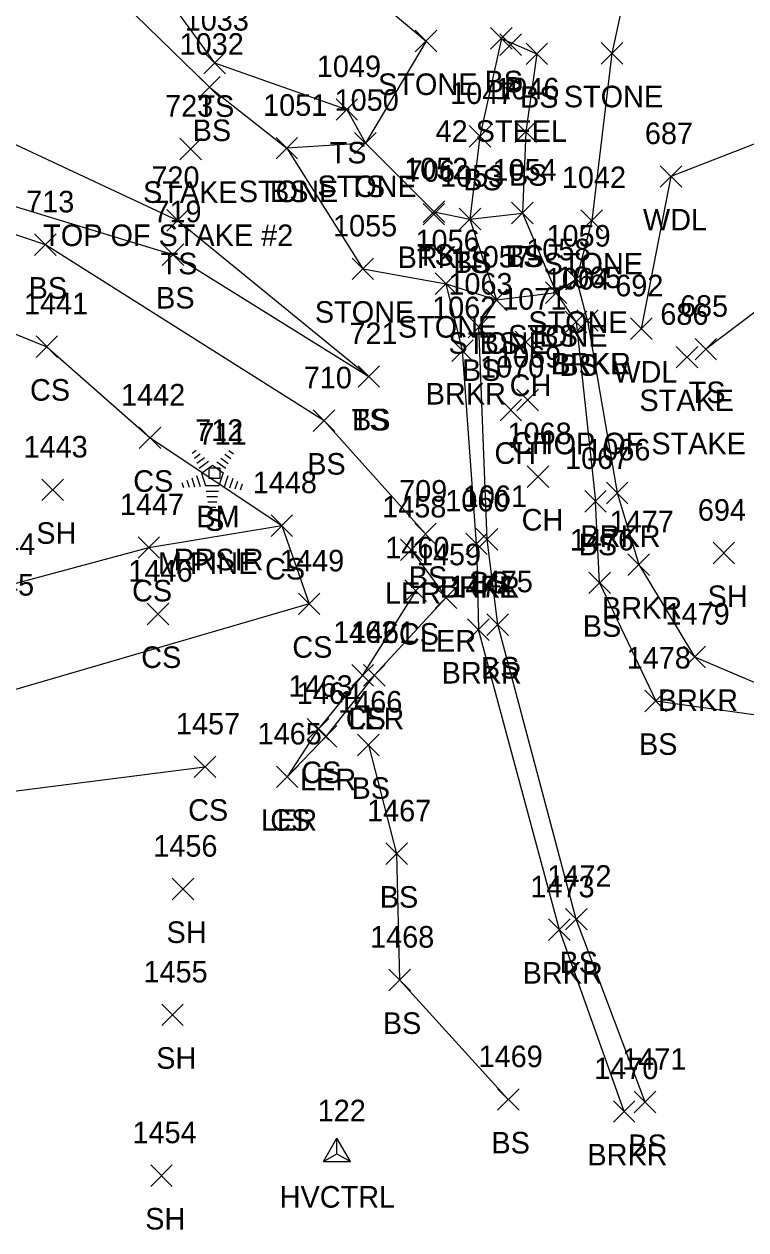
# Model space of a CAD drawing. Extents: x 1485624 to 1495982, y 886445 to 890805.
# Drawn here: x 1495677.5 to 1495744.5, y 890408.1 to 890519.9 of the extents above; entities that cross this region are included whole.
import ezdxf

# ---------------------------------------------------------------- set-up
doc = ezdxf.new("R2010")
doc.units = 0
for name, color, linetype in [('C_A', 7, 'Continuous'), ('C_C', 7, 'Continuous'), ('C_I', 7, 'Continuous'), ('CPBM', 7, 'Continuous'), ('CPSM', 7, 'Continuous'), ('D_A', 7, 'Continuous'), ('D_C', 7, 'Continuous'), ('D_TIC', 7, 'Continuous'), ('E_TIC', 7, 'Continuous'), ('L_A', 7, 'Continuous'), ('L_C', 7, 'Continuous'), ('L_I', 7, 'Continuous'), ('L_TIC', 7, 'Continuous'), ('LARO', 7, 'Continuous'), ('LASF', 7, 'Continuous'), ('LAWA', 7, 'Continuous'), ('LAWE', 7, 'Continuous'), ('LELB', 7, 'Continuous'), ('LTC', 7, 'Continuous'), ('P_I', 7, 'Continuous')]:
    doc.layers.add(name, color=color, linetype=linetype)

msp = doc.modelspace()

# ---------------------------------------------------------------- linework, layer by layer
at = {"layer": 'CPBM'}
for p, q in [((1495694.68, 890477.73), (1495694.68, 890478.73)), ((1495694.68, 890478.73), (1495695.68, 890478.73)), ((1495695.68, 890477.73), (1495694.68, 890477.73)), ((1495695.18, 890478.23), (1495695.18, 890478.23)), ((1495695.18, 890478.23), (1495695.18, 890478.23)), ((1495695.68, 890478.73), (1495695.68, 890477.73))]:
    msp.add_line(p, q, dxfattribs=at)
at = {"layer": 'CPSM'}
for p, q in [((1495705.29, 890414.44), (1495706.54, 890416.6)), ((1495707.79, 890414.44), (1495706.54, 890416.6)), ((1495706.54, 890415.16), (1495706.54, 890416.6)), ((1495705.29, 890414.44), (1495706.54, 890415.16)), ((1495706.54, 890415.16), (1495706.54, 890415.16)), ((1495706.54, 890415.16), (1495707.79, 890414.44)), ((1495705.29, 890414.44), (1495707.79, 890414.44))]:
    msp.add_line(p, q, dxfattribs=at)
at = {"layer": 'D_TIC'}
for points in [[(1495721.65, 890516.95), (1495723.65, 890518.95)], [(1495723.65, 890516.95), (1495721.65, 890518.95)]]:
    msp.add_lwpolyline(points, dxfattribs=at)
at = {"layer": 'E_TIC'}
for points in [[(1495691.97, 890507.29), (1495693.97, 890509.29)], [(1495693.97, 890507.29), (1495691.97, 890509.29)], [(1495737.99, 890487.99), (1495739.99, 890489.99)], [(1495739.99, 890487.99), (1495737.99, 890489.99)]]:
    msp.add_lwpolyline(points, dxfattribs=at)
at = {"layer": 'L_TIC'}
for points in [[(1495713.8, 890517.29), (1495715.8, 890519.29)], [(1495715.8, 890517.29), (1495713.8, 890519.29)], [(1495720.78, 890517.54), (1495722.78, 890519.54)], [(1495722.78, 890517.54), (1495720.78, 890519.54)], [(1495720.78, 890517.54), (1495722.78, 890519.54)], [(1495722.78, 890517.54), (1495720.78, 890519.54)], [(1495724.07, 890516.11), (1495726.07, 890518.11)], [(1495726.07, 890516.11), (1495724.07, 890518.11)], [(1495731.03, 890516.15), (1495733.03, 890518.15)], [(1495733.03, 890516.15), (1495731.03, 890518.15)], [(1495694.19, 890515.26), (1495696.19, 890517.26)], [(1495696.19, 890515.26), (1495694.19, 890517.26)], [(1495693.72, 890513.02), (1495695.72, 890515.02)], [(1495695.72, 890513.02), (1495693.72, 890515.02)], [(1495706.45, 890510.95), (1495708.45, 890512.95)], [(1495708.45, 890510.95), (1495706.45, 890512.95)], [(1495718.8, 890508.46), (1495720.8, 890510.46)], [(1495720.8, 890508.46), (1495718.8, 890510.46)], [(1495723.04, 890508.88), (1495725.04, 890510.88)], [(1495725.04, 890508.88), (1495723.04, 890510.88)], [(1495700.89, 890507.36), (1495702.89, 890509.36)], [(1495702.89, 890507.36), (1495700.89, 890509.36)], [(1495700.89, 890507.36), (1495702.89, 890509.36)], [(1495702.89, 890507.36), (1495700.89, 890509.36)], [(1495708.18, 890507.83), (1495710.18, 890509.83)], [(1495710.18, 890507.83), (1495708.18, 890509.83)], [(1495708.18, 890507.83), (1495710.18, 890509.83)], [(1495710.18, 890507.83), (1495708.18, 890509.83)], [(1495736.5, 890504.74), (1495738.5, 890506.74)], [(1495738.5, 890504.74), (1495736.5, 890506.74)], [(1495714.54, 890501.47), (1495716.54, 890503.47)], [(1495716.54, 890501.47), (1495714.54, 890503.47)], [(1495690.78, 890500.67), (1495692.78, 890502.67)], [(1495692.78, 890500.67), (1495690.78, 890502.67)], [(1495714.52, 890501.25), (1495716.52, 890503.25)], [(1495716.52, 890501.25), (1495714.52, 890503.25)], [(1495717.87, 890500.79), (1495719.87, 890502.79)], [(1495719.87, 890500.79), (1495717.87, 890502.79)], [(1495717.87, 890500.79), (1495719.87, 890502.79)], [(1495719.87, 890500.79), (1495717.87, 890502.79)], [(1495722.73, 890501.35), (1495724.73, 890503.35)], [(1495724.73, 890501.35), (1495722.73, 890503.35)], [(1495722.73, 890501.35), (1495724.73, 890503.35)], [(1495724.73, 890501.35), (1495722.73, 890503.35)], [(1495729.16, 890500.66), (1495731.16, 890502.66)], [(1495731.16, 890500.66), (1495729.16, 890502.66)], [(1495678.51, 890498.41), (1495680.51, 890500.41)], [(1495680.51, 890498.41), (1495678.51, 890500.41)], [(1495690.33, 890497.5), (1495692.33, 890499.5)], [(1495692.33, 890497.5), (1495690.33, 890499.5)], [(1495707.94, 890496.18), (1495709.94, 890498.18)], [(1495709.94, 890496.18), (1495707.94, 890498.18)], [(1495715.65, 890494.8), (1495717.65, 890496.8)], [(1495717.65, 890494.8), (1495715.65, 890496.8)], [(1495727.74, 890495.24), (1495729.74, 890497.24)], [(1495729.74, 890495.24), (1495727.74, 890497.24)], [(1495727.74, 890495.24), (1495729.74, 890497.24)], [(1495729.74, 890495.24), (1495727.74, 890497.24)], [(1495725.86, 890493.97), (1495727.86, 890495.97)], [(1495727.86, 890493.97), (1495725.86, 890495.97)], [(1495725.86, 890493.97), (1495727.86, 890495.97)], [(1495727.86, 890493.97), (1495725.86, 890495.97)], [(1495720.33, 890493.3), (1495722.33, 890495.3)], [(1495722.33, 890493.3), (1495720.33, 890495.3)], [(1495720.33, 890493.3), (1495722.33, 890495.3)], [(1495722.33, 890493.3), (1495720.33, 890495.3)], [(1495728.77, 890491.39), (1495730.77, 890493.39)], [(1495730.77, 890491.39), (1495728.77, 890493.39)], [(1495728.77, 890491.39), (1495730.77, 890493.39)], [(1495730.77, 890491.39), (1495728.77, 890493.39)], [(1495718.69, 890490.79), (1495720.69, 890492.79)], [(1495720.69, 890490.79), (1495718.69, 890492.79)], [(1495727.71, 890491.26), (1495729.71, 890493.26)], [(1495729.71, 890491.26), (1495727.71, 890493.26)], [(1495733.75, 890490.63), (1495735.75, 890492.63)], [(1495735.75, 890490.63), (1495733.75, 890492.63)], [(1495723.06, 890489.39), (1495725.06, 890491.39)], [(1495725.06, 890489.39), (1495723.06, 890491.39)], [(1495678.64, 890488.96), (1495680.64, 890490.96)], [(1495680.64, 890488.96), (1495678.64, 890490.96)], [(1495717.18, 890488.6), (1495719.18, 890490.6)], [(1495719.18, 890488.6), (1495717.18, 890490.6)], [(1495739.74, 890488.73), (1495741.74, 890490.73)], [(1495741.74, 890488.73), (1495739.74, 890490.73)], [(1495708.49, 890486.2), (1495710.49, 890488.2)], [(1495710.49, 890486.2), (1495708.49, 890488.2)], [(1495708.49, 890486.2), (1495710.49, 890488.2)], [(1495710.49, 890486.2), (1495708.49, 890488.2)], [(1495723.21, 890484.03), (1495725.21, 890486.03)], [(1495725.21, 890484.03), (1495723.21, 890486.03)], [(1495721.66, 890483.1), (1495723.66, 890485.1)], [(1495723.66, 890483.1), (1495721.66, 890485.1)], [(1495704.34, 890482.1), (1495706.34, 890484.1)], [(1495706.34, 890482.1), (1495704.34, 890484.1)], [(1495688.21, 890480.51), (1495690.21, 890482.51)], [(1495690.21, 890480.51), (1495688.21, 890482.51)], [(1495724.17, 890476.92), (1495726.17, 890478.92)], [(1495726.17, 890476.92), (1495724.17, 890478.92)], [(1495679.17, 890475.69), (1495681.17, 890477.69)], [(1495681.17, 890475.69), (1495679.17, 890477.69)], [(1495729.51, 890474.63), (1495731.51, 890476.63)], [(1495731.51, 890474.63), (1495729.51, 890476.63)], [(1495731.52, 890475.41), (1495733.52, 890477.41)], [(1495733.52, 890475.41), (1495731.52, 890477.41)], [(1495700.43, 890472.38), (1495702.43, 890474.38)], [(1495702.43, 890472.38), (1495700.43, 890474.38)], [(1495700.43, 890472.38), (1495702.43, 890474.38)], [(1495702.43, 890472.38), (1495700.43, 890474.38)], [(1495713.75, 890471.6), (1495715.75, 890473.6)], [(1495715.75, 890471.6), (1495713.75, 890473.6)], [(1495688.1, 890470.35), (1495690.1, 890472.35)], [(1495690.1, 890470.35), (1495688.1, 890472.35)], [(1495712.42, 890470.13), (1495714.42, 890472.13)], [(1495714.42, 890470.13), (1495712.42, 890472.13)], [(1495718.48, 890470.69), (1495720.48, 890472.69)], [(1495720.48, 890470.69), (1495718.48, 890472.69)], [(1495718.48, 890470.69), (1495720.48, 890472.69)], [(1495720.48, 890470.69), (1495718.48, 890472.69)], [(1495719.46, 890471.1), (1495721.46, 890473.1)], [(1495721.46, 890471.1), (1495719.46, 890473.1)], [(1495741.41, 890469.83), (1495743.41, 890471.83)], [(1495743.41, 890469.83), (1495741.41, 890471.83)], [(1495733.52, 890468.76), (1495735.52, 890470.76)], [(1495735.52, 890468.76), (1495733.52, 890470.76)], [(1495729.89, 890467.07), (1495731.89, 890469.07)], [(1495731.89, 890467.07), (1495729.89, 890469.07)], [(1495712.84, 890466.34), (1495714.84, 890468.34)], [(1495714.84, 890466.34), (1495712.84, 890468.34)], [(1495715.65, 890465.7), (1495717.65, 890467.7)], [(1495717.65, 890465.7), (1495715.65, 890467.7)], [(1495702.96, 890465.13), (1495704.96, 890467.13)], [(1495704.96, 890465.13), (1495702.96, 890467.13)], [(1495702.96, 890465.13), (1495704.96, 890467.13)], [(1495704.96, 890465.13), (1495702.96, 890467.13)], [(1495688.95, 890464.18), (1495690.95, 890466.18)], [(1495690.95, 890464.18), (1495688.95, 890466.18)], [(1495718.65, 890462.74), (1495720.65, 890464.74)], [(1495720.65, 890462.74), (1495718.65, 890464.74)], [(1495720.44, 890463.2), (1495722.44, 890465.2)], [(1495722.44, 890463.2), (1495720.44, 890465.2)], [(1495738.7, 890460.2), (1495740.7, 890462.2)], [(1495740.7, 890460.2), (1495738.7, 890462.2)], [(1495707.92, 890458.51), (1495709.92, 890460.51)], [(1495709.92, 890458.51), (1495707.92, 890460.51)], [(1495709, 890458.49), (1495711, 890460.49)], [(1495711, 890458.49), (1495709, 890460.49)], [(1495735.09, 890456.13), (1495737.09, 890458.13)], [(1495737.09, 890456.13), (1495735.09, 890458.13)], [(1495703.79, 890453.51), (1495705.79, 890455.51)], [(1495705.79, 890453.51), (1495703.79, 890455.51)], [(1495704.54, 890452.85), (1495706.54, 890454.85)], [(1495706.54, 890452.85), (1495704.54, 890454.85)], [(1495708.45, 890452.05), (1495710.45, 890454.05)], [(1495710.45, 890452.05), (1495708.45, 890454.05)], [(1495693.3, 890450.02), (1495695.3, 890452.02)], [(1495695.3, 890450.02), (1495693.3, 890452.02)], [(1495700.92, 890449.09), (1495702.92, 890451.09)], [(1495702.92, 890449.09), (1495700.92, 890451.09)], [(1495700.92, 890449.09), (1495702.92, 890451.09)], [(1495702.92, 890449.09), (1495700.92, 890451.09)], [(1495711.07, 890441.96), (1495713.07, 890443.96)], [(1495713.07, 890441.96), (1495711.07, 890443.96)], [(1495691.26, 890438.69), (1495693.26, 890440.69)], [(1495693.26, 890438.69), (1495691.26, 890440.69)], [(1495727.73, 890435.9), (1495729.73, 890437.9)], [(1495729.73, 890435.9), (1495727.73, 890437.9)], [(1495726.16, 890434.92), (1495728.16, 890436.92)], [(1495728.16, 890434.92), (1495726.16, 890436.92)], [(1495711.35, 890430.26), (1495713.35, 890432.26)], [(1495713.35, 890430.26), (1495711.35, 890432.26)], [(1495690.29, 890427.03), (1495692.29, 890429.03)], [(1495692.29, 890427.03), (1495690.29, 890429.03)], [(1495721.42, 890419.18), (1495723.42, 890421.18)], [(1495723.42, 890419.18), (1495721.42, 890421.18)], [(1495734.11, 890418.94), (1495736.11, 890420.94)], [(1495736.11, 890418.94), (1495734.11, 890420.94)], [(1495732.17, 890418.07), (1495734.17, 890420.07)], [(1495734.17, 890418.07), (1495732.17, 890420.07)], [(1495689.27, 890412.13), (1495691.27, 890414.13)], [(1495691.27, 890412.13), (1495689.27, 890414.13)]]:
    msp.add_lwpolyline(points, dxfattribs=at)
at = {"layer": 'LARO'}
msp.add_lwpolyline([(1495713.42, 890471.13), (1495716.65, 890466.7), (1495710, 890459.49), (1495705.54, 890453.85), (1495701.92, 890450.09)], dxfattribs=at)
at = {"layer": 'LASF'}
for points in [[(1495706.41, 890525.35), (1495715.59, 890530.6), (1495727.73, 890532.52), (1495739.27, 890540.91), (1495733.8, 890525.29), (1495732.03, 890517.15), (1495730.16, 890501.66), (1495728.74, 890496.24)], [(1495706.41, 890525.35), (1495714.8, 890518.29), (1495709.18, 890508.83), (1495701.89, 890508.36), (1495708.94, 890497.18), (1495716.65, 890495.8), (1495721.33, 890494.3), (1495726.86, 890494.97), (1495728.74, 890496.24)]]:
    msp.add_lwpolyline(points, dxfattribs=at)
at = {"layer": 'LAWA'}
msp.add_lwpolyline([(1495845.33, 890503.1), (1495828.07, 890498.9), (1495801.7, 890510.81), (1495780.01, 890514.68), (1495754.98, 890512.53), (1495737.5, 890505.74), (1495734.75, 890491.63)], dxfattribs=at)
at = {"layer": 'LAWE'}
for points in [[(1495718.18, 890489.6), (1495716.65, 890495.8)], [(1495729.77, 890492.39), (1495728.74, 890496.24)], [(1495729.77, 890492.39), (1495732.52, 890476.41)], [(1495719.48, 890471.69), (1495718.18, 890489.6)], [(1495732.52, 890476.41), (1495734.52, 890469.76)], [(1495719.48, 890471.69), (1495719.65, 890463.74)], [(1495734.52, 890469.76), (1495739.7, 890461.2), (1495751.82, 890456.06), (1495759.64, 890451.71), (1495762.76, 890439.13)], [(1495733.17, 890419.07), (1495727.16, 890435.92), (1495719.65, 890463.74)]]:
    msp.add_lwpolyline(points, dxfattribs=at)
at = {"layer": 'LELB'}
for points in [[(1495650.44, 890558.06), (1495659.47, 890551.56), (1495670.67, 890542.5), (1495680.95, 890527.45), (1495694.72, 890514.02), (1495701.89, 890508.36)], [(1495739.03, 890547.65), (1495724.1, 890552.5), (1495699.75, 890551.1), (1495679.27, 890557.9), (1495679.11, 890557.89), (1495668.33, 890556.32), (1495662.04, 890554.8), (1495672.43, 890545.26), (1495683.67, 890532.06), (1495695.19, 890516.26), (1495707.45, 890511.95), (1495709.18, 890508.83), (1495715.54, 890502.47), (1495718.87, 890501.79), (1495723.73, 890502.35)], [(1495639, 890524.66), (1495645.41, 890543.3), (1495656.07, 890524.09), (1495671.2, 890504.61), (1495691.33, 890498.5), (1495709.49, 890487.2)], [(1495757.57, 890537.9), (1495788.35, 890527.83), (1495828.07, 890498.9), (1495795.98, 890501.66), (1495778.3, 890500.66), (1495774.03, 890506.35), (1495756.49, 890501.63), (1495740.74, 890489.73)], [(1495657.47, 890527.66), (1495666.08, 890513.68), (1495691.78, 890501.67), (1495709.49, 890487.2)], [(1495721.78, 890518.54), (1495719.8, 890509.46), (1495718.87, 890501.79), (1495721.33, 890494.3)], [(1495721.78, 890518.54), (1495725.07, 890517.11), (1495724.04, 890509.88), (1495723.73, 890502.35), (1495726.86, 890494.97)], [(1495644.28, 890509.68), (1495663.89, 890496.33), (1495679.64, 890489.96), (1495689.21, 890481.51), (1495701.43, 890473.38), (1495703.96, 890466.13), (1495674.38, 890457.51)], [(1495714.75, 890472.6), (1495705.34, 890483.1), (1495679.51, 890499.41), (1495654.42, 890507.9)], [(1495728.71, 890492.26), (1495726.86, 890494.97)], [(1495719.69, 890491.79), (1495721.33, 890494.3)], [(1495728.71, 890492.26), (1495730.51, 890475.63)], [(1495720.46, 890472.1), (1495719.69, 890491.79)], [(1495730.89, 890468.07), (1495730.51, 890475.63)], [(1495675.31, 890467.65), (1495689.1, 890471.35), (1495701.43, 890473.38)], [(1495721.44, 890464.2), (1495720.46, 890472.1)], [(1495730.89, 890468.07), (1495736.09, 890457.13), (1495749.43, 890455.27), (1495756.63, 890449.59), (1495760.24, 890438.39)], [(1495713.84, 890467.34), (1495708.92, 890459.51), (1495704.79, 890454.51), (1495701.92, 890450.09)], [(1495735.11, 890419.94), (1495728.73, 890436.9), (1495721.44, 890464.2)], [(1495709.45, 890453.05), (1495712.07, 890442.96), (1495712.35, 890431.26), (1495722.42, 890420.18)], [(1495669.3, 890447.84), (1495694.3, 890451.02)]]:
    msp.add_lwpolyline(points, dxfattribs=at)
at = {"layer": 'LTC'}
for p, q in [((1495693.12, 890480.1), (1495693.48, 890480.36)), ((1495693.33, 890479.63), (1495693.86, 890480.02)), ((1495696.15, 890479.99), (1495696.7, 890479.59)), ((1495696.52, 890480.34), (1495696.94, 890480.03)), ((1495693.54, 890479.17), (1495694.25, 890479.68)), ((1495693.75, 890478.7), (1495694.63, 890479.34)), ((1495693.98, 890478.25), (1495694.99, 890478.98)), ((1495694.99, 890478.98), (1495695.99, 890478.26)), ((1495695.41, 890479.29), (1495696.22, 890478.7)), ((1495695.78, 890479.64), (1495696.46, 890479.15)), ((1495693.07, 890477.81), (1495693.34, 890476.97)), ((1495693.52, 890478.03), (1495693.85, 890477.01)), ((1495693.98, 890478.25), (1495694.36, 890477.05)), ((1495695.99, 890478.26), (1495695.59, 890477.05)), ((1495696.42, 890477.98), (1495696.08, 890476.94)), ((1495696.87, 890477.73), (1495696.58, 890476.85)), ((1495692.16, 890477.38), (1495692.31, 890476.91)), ((1495692.61, 890477.59), (1495692.82, 890476.94)), ((1495695.59, 890477.05), (1495694.36, 890477.05)), ((1495695.56, 890476.55), (1495694.41, 890476.55)), ((1495697.31, 890477.48), (1495697.07, 890476.75)), ((1495697.76, 890477.23), (1495697.57, 890476.66)), ((1495695.47, 890476.05), (1495694.48, 890476.05)), ((1495695.39, 890475.55), (1495694.56, 890475.55)), ((1495695.3, 890475.05), (1495694.63, 890475.05))]:
    msp.add_line(p, q, dxfattribs=at)

# ---------------------------------------------------------------- texts
at = {"layer": 'C_A'}
for s, p in [('STAKE', (1495688.56, 890503.29)), ('STAKE', (1495734.58, 890483.99)), ('BM', (1495693.5, 890473.23)), ('HVCTRL', (1495701.23, 890410.16))]:
    msp.add_text(s, height=2, dxfattribs=at).set_placement(p)
at = {"layer": 'C_C'}
for s, p in [('TOP OF STAKE #2', (1495679.3, 890499.29)), ('TOP OF STAKE # 1', (1495724.99, 890479.99)), ('RRSIR', (1495691.4, 890469.23))]:
    msp.add_text(s, height=2, dxfattribs=at).set_placement(p)
at = {"layer": 'C_I'}
for s, p in [('723', (1495690.61, 890511.29)), ('686', (1495736.52, 890491.99)), ('712', (1495693.39, 890481.23)), ('122', (1495704.75, 890418.16))]:
    msp.add_text(s, height=2, dxfattribs=at).set_placement(p)
at = {"layer": 'D_A'}
msp.add_text('P', height=2, dxfattribs=at).set_placement((1495722.03, 890512.95))
at = {"layer": 'D_C'}
msp.add_text('42 STEEL', height=2, dxfattribs=at).set_placement((1495715.68, 890508.95))
at = {"layer": 'L_A'}
for s, p in [('STONE', (1495710.35, 890513.29)), ('BS', (1495720.22, 890513.54)), ('BS', (1495720.22, 890513.54)), ('BS', (1495723.51, 890512.11)), ('STONE', (1495727.57, 890512.15)), ('TS', (1495693.6, 890511.26)), ('BS', (1495693.16, 890509.02)), ('TS', (1495705.86, 890506.95)), ('BS', (1495722.48, 890504.88)), ('STONE', (1495704.72, 890503.83)), ('TS', (1495707.59, 890503.83)), ('BS', (1495718.24, 890504.46)), ('STONE', (1495697.44, 890503.36)), ('BS', (1495700.33, 890503.36)), ('WDL', (1495734.91, 890500.74)), ('BRKL', (1495712.16, 890497.25)), ('TS', (1495713.95, 890497.47)), ('TS', (1495722.14, 890497.35)), ('BS', (1495722.17, 890497.35)), ('TS', (1495690.19, 890496.67)), ('TS', (1495717.28, 890496.79)), ('BS', (1495717.31, 890496.79)), ('STONE', (1495725.7, 890496.66)), ('BS', (1495677.95, 890494.41)), ('BS', (1495689.77, 890493.5)), ('STONE', (1495704.49, 890492.18)), ('STONE', (1495712.19, 890490.8)), ('STONE', (1495724.28, 890491.24)), ('STONE', (1495724.28, 890491.24)), ('STONE', (1495716.87, 890489.3)), ('BS', (1495719.77, 890489.3)), ('STONE', (1495722.41, 890489.97)), ('BS', (1495725.31, 890489.97)), ('BRKR', (1495726.36, 890487.39)), ('BRKL', (1495726.42, 890487.39)), ('BS', (1495727.15, 890487.26)), ('BS', (1495718.13, 890486.79)), ('WDL', (1495732.16, 890486.63)), ('CS', (1495678.08, 890484.96)), ('BRKR', (1495714.77, 890484.6)), ('CH', (1495722.55, 890485.39)), ('TS', (1495739.15, 890484.73)), ('TS', (1495707.9, 890482.2)), ('BS', (1495707.93, 890482.2)), ('CH', (1495721.14, 890479.1)), ('CH', (1495722.7, 890480.03)), ('BS', (1495703.78, 890478.1)), ('CS', (1495687.65, 890476.51)), ('S', (1495694.31, 890472.89)), ('CH', (1495723.66, 890472.92)), ('SH', (1495678.66, 890471.69)), ('BRKR', (1495729.11, 890471.41)), ('BS', (1495728.95, 890470.63)), ('CS', (1495699.87, 890468.38)), ('CS', (1495699.87, 890468.38)), ('BS', (1495713.19, 890467.6)), ('BS', (1495718.9, 890467.1)), ('CS', (1495687.54, 890466.35)), ('LER', (1495711, 890466.13)), ('BRKR', (1495716.07, 890466.69)), ('BRKL', (1495716.13, 890466.69)), ('SH', (1495740.9, 890465.83)), ('BRKR', (1495731.11, 890464.76)), ('CS', (1495712.28, 890462.34)), ('BS', (1495729.33, 890463.07)), ('CS', (1495702.4, 890461.13)), ('CS', (1495702.4, 890461.13)), ('LER', (1495714.24, 890461.7)), ('CS', (1495688.39, 890460.18)), ('BS', (1495719.88, 890459.2)), ('BRKR', (1495716.24, 890458.74)), ('BRKR', (1495736.29, 890456.2)), ('CS', (1495707.36, 890454.51)), ('LER', (1495707.58, 890454.49)), ('BS', (1495734.54, 890452.13)), ('LER', (1495703.12, 890448.85)), ('CS', (1495703.23, 890449.51)), ('BS', (1495707.89, 890448.05)), ('CS', (1495692.74, 890446.02)), ('LER', (1495699.5, 890445.09)), ('CS', (1495700.36, 890445.09)), ('BS', (1495710.51, 890437.96)), ('SH', (1495690.74, 890434.69)), ('BS', (1495727.17, 890431.9)), ('BRKR', (1495723.75, 890430.92)), ('BS', (1495710.79, 890426.26)), ('SH', (1495689.78, 890423.03)), ('BS', (1495720.86, 890415.18)), ('BS', (1495733.55, 890414.94)), ('BRKR', (1495729.76, 890414.07)), ('SH', (1495688.76, 890408.13))]:
    msp.add_text(s, height=2, dxfattribs=at).set_placement(p)
at = {"layer": 'L_C'}
msp.add_text('M PINE', height=2, dxfattribs=at).set_placement((1495689.95, 890468.89))
at = {"layer": 'L_I'}
for s, p in [('1033', (1495692.42, 890519.26)), ('1032', (1495691.95, 890517.02)), ('1049', (1495704.67, 890514.95)), ('1046', (1495721.21, 890512.88)), ('1050', (1495706.32, 890511.83)), ('1050', (1495706.32, 890511.83)), ('1047', (1495717.03, 890512.46)), ('1051', (1495699.69, 890511.36)), ('1051', (1495699.69, 890511.36)), ('687', (1495735.09, 890508.74)), ('1052', (1495712.77, 890505.47)), ('706', (1495713.02, 890505.25)), ('1053', (1495716.09, 890504.79)), ('1053', (1495716.09, 890504.79)), ('1054', (1495720.96, 890505.35)), ('1054', (1495720.96, 890505.35)), ('720', (1495689.33, 890504.67)), ('1042', (1495727.39, 890504.66)), ('713', (1495677.72, 890502.41)), ('719', (1495689.52, 890501.5)), ('1055', (1495706.17, 890500.18)), ('1059', (1495725.96, 890499.24)), ('1059', (1495725.96, 890499.24)), ('1056', (1495713.82, 890498.8)), ('1057', (1495718.56, 890497.3)), ('1057', (1495718.56, 890497.3)), ('1058', (1495724.09, 890497.97)), ('1058', (1495724.09, 890497.97)), ('1063', (1495716.87, 890494.79)), ('1064', (1495725.89, 890495.26)), ('1065', (1495726.95, 890495.39)), ('1065', (1495726.95, 890495.39)), ('692', (1495732.34, 890494.63)), ('1441', (1495677.52, 890492.96)), ('1062', (1495715.36, 890492.6)), ('1071', (1495721.86, 890493.39)), ('685', (1495738.34, 890492.73)), ('721', (1495707.69, 890490.2)), ('721', (1495707.69, 890490.2)), ('1069', (1495721.38, 890488.03)), ('1070', (1495719.8, 890487.1)), ('710', (1495703.46, 890486.1)), ('1442', (1495686.52, 890484.51)), ('711', (1495693.7, 890480.89)), ('1068', (1495722.35, 890480.92)), ('1443', (1495677.48, 890479.69)), ('1066', (1495729.65, 890479.41)), ('1067', (1495727.69, 890478.63)), ('1448', (1495698.73, 890476.38)), ('1448', (1495698.73, 890476.38)), ('709', (1495712.3, 890475.6)), ('1060', (1495716.58, 890474.69)), ('1060', (1495716.58, 890474.69)), ('1061', (1495718.21, 890475.1)), ('1447', (1495686.41, 890474.35)), ('1458', (1495710.73, 890474.13)), ('694', (1495740, 890473.83)), ('1477', (1495731.82, 890472.76)), ('1444', (1495672.62, 890470.65)), ('1460', (1495711.02, 890470.34)), ('1476', (1495728.14, 890471.07)), ('1449', (1495701.26, 890469.13)), ('1449', (1495701.26, 890469.13)), ('1459', (1495713.95, 890469.7)), ('1446', (1495687.2, 890468.18)), ('1445', (1495672.51, 890466.89)), ('1474', (1495716.95, 890466.74)), ('1475', (1495718.75, 890467.2)), ('1479', (1495737, 890464.2)), ('1462', (1495706.18, 890462.51)), ('1461', (1495707.83, 890462.49)), ('1478', (1495733.4, 890460.13)), ('1463', (1495702.05, 890457.51)), ('1464', (1495702.8, 890456.85)), ('1466', (1495706.65, 890456.05)), ('1457', (1495691.61, 890454.02)), ('1465', (1495699.18, 890453.09)), ('1465', (1495699.18, 890453.09)), ('1467', (1495709.33, 890445.96)), ('1456', (1495689.51, 890442.69)), ('1472', (1495726.04, 890439.9)), ('1473', (1495724.47, 890438.92)), ('1468', (1495709.61, 890434.26)), ('1455', (1495688.6, 890431.03)), ('1469', (1495719.67, 890423.18)), ('1470', (1495730.39, 890422.07)), ('1471', (1495732.99, 890422.94)), ('1454', (1495687.58, 890416.13))]:
    msp.add_text(s, height=2, dxfattribs=at).set_placement(p)
at = {"layer": 'LTC'}
msp.add_text('.', height=1.04, rotation=270, dxfattribs=at).set_placement((1495694.87, 890477.99))
at = {"layer": 'P_I'}
msp.add_text('1444', height=2, dxfattribs=at).set_placement((1495672.62, 890470.65))

doc.saveas('drawing.dxf')
